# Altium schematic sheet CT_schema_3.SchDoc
size 276 x 169 mm
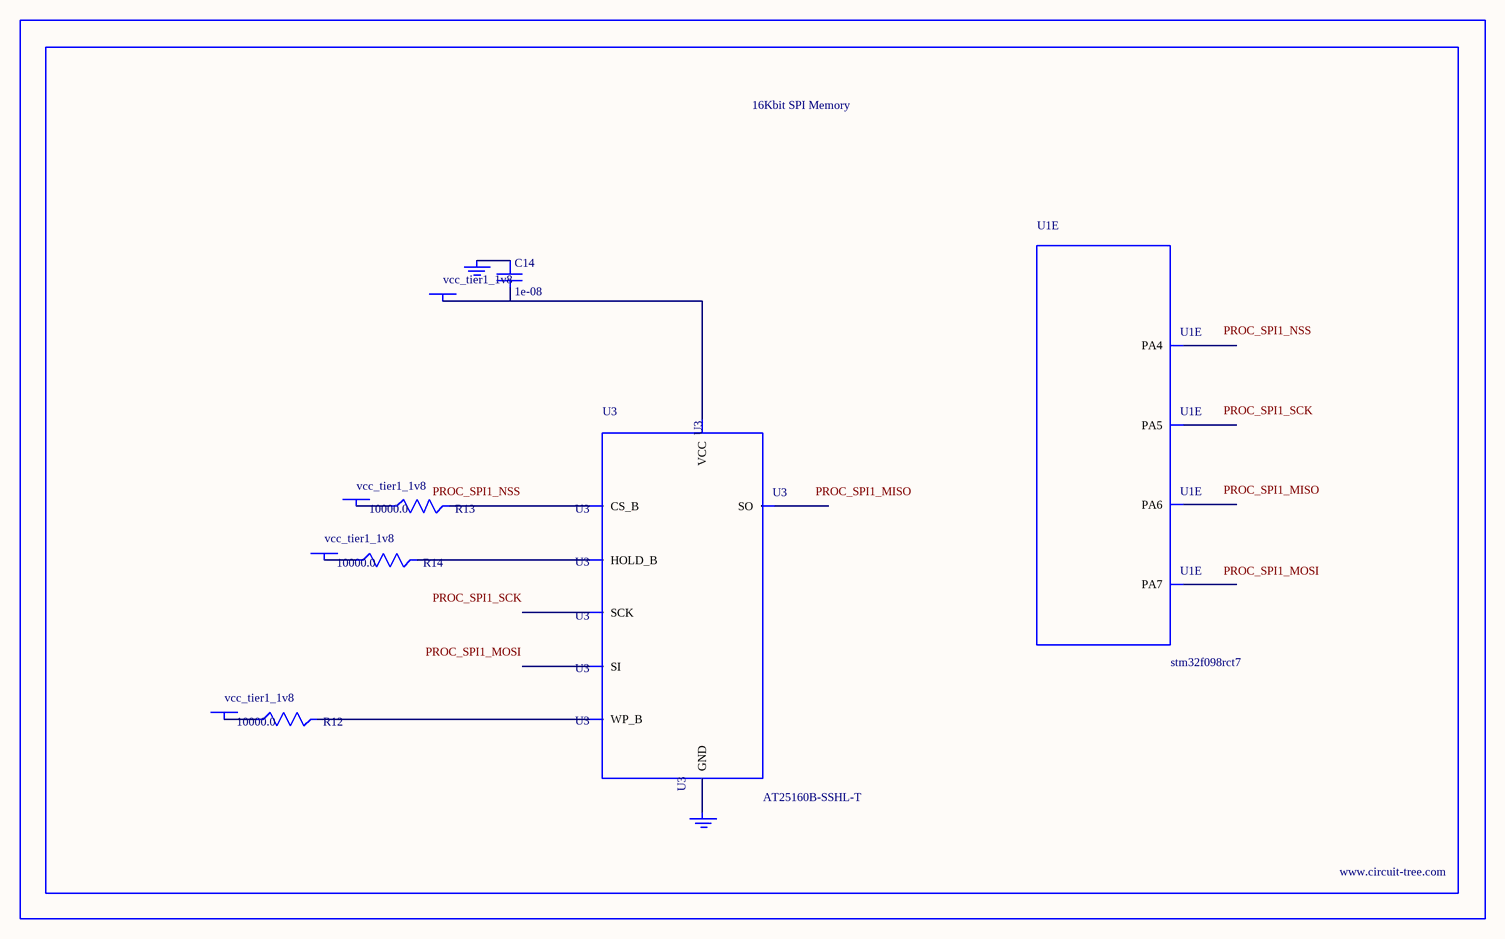
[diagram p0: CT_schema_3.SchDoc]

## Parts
BORDER2  (no value)
C14  1e-08  [C0402]
GND_INSTANCE_2_0  (no value)
GND_INSTANCE_2_1  (no value)
POWER_INSTANCE_2_0  vcc_tier1_1v8
POWER_INSTANCE_2_1  vcc_tier1_1v8
POWER_INSTANCE_2_2  vcc_tier1_1v8
POWER_INSTANCE_2_3  vcc_tier1_1v8
R12  10000.0  [R0603]
R13  10000.0  [R0603]
R14  10000.0  [R0603]
U1  stm32f098rct7  [LQFP64]  (part E of 7)
U3  AT25160B-SSHL-T  [SOIC-8]

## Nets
NetC14_1: C14.1 GND_INSTANCE_2_0.0(GND)
NetC14_2: C14.2 POWER_INSTANCE_2_3.0(PWR) U3.8(VCC)
NetGND_INSTANCE_2_1_0: GND_INSTANCE_2_1.0(GND) U3.4(GND)
NetPOWER_INSTANCE_2_0_0: POWER_INSTANCE_2_0.0(PWR) R13.1
NetPOWER_INSTANCE_2_1_0: POWER_INSTANCE_2_1.0(PWR) R12.1
NetPOWER_INSTANCE_2_2_0: POWER_INSTANCE_2_2.0(PWR) R14.1
NetR12_2: R12.2 U3.3(WP_B)
NetR13_2: R13.2 U3.1(CS_B)
NetR14_2: R14.2 U3.7(HOLD_B)

Not connected (* = marked no-connect by the designer): U1 20(PA4) 21(PA5) 22(PA6) 23(PA7); U3 2(SO) 5(SI) 6(SCK)

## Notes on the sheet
- Labels drawn without touching a wire or pin: PROC_SPI1_MISO, PROC_SPI1_MOSI, PROC_SPI1_NSS, PROC_SPI1_SCK

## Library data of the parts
BORDER2 = BORDER_PAGE2
C14 = C0402C103K3RAC
GND_INSTANCE_2_0 GND_INSTANCE_2_1 = GND
POWER_INSTANCE_2_0-POWER_INSTANCE_2_3 = PWR
R12-R14 = RC0603JR-0710KL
